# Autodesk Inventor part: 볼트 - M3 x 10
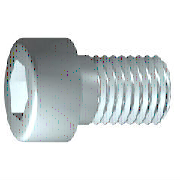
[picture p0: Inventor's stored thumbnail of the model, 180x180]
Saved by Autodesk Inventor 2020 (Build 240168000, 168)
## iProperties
Created: 2012-02
Part Number: 볼트 - M3 x 10
Material: 스테인리스강
Description: 6각 소켓 머리 캡 나사
Document SubType Name: Modeling
Standard: ISO 4762
Designer: mduedu
Standard Revision: Fourth edition 2004-03-01
Standards Organization: ISO
Language: ko-KR
Size Designation: M3 x 10
Categories: <MemberInstance><Categories><Category DisplayName="조임쇠" InternalName="e4da775c-781d-43d5-af7c-5136215cf5a6" Mnemonic="FSTN"><Category DisplayName="볼트" InternalN
Density: 8.08 g/cm^3
Mass: 1.0701 g
Surface Area: 2.01851 cm^2
Volume: 0.132438 cm^3
Appearance: 반광택
IsCustomPart: 0
Author: mduedu
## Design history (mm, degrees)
sketch "스케치1"
  geometry: L1 (-0.867, 0)-(10, 0); L2 (10, 0)-(10, 1.5); L3 (10, 1.5)-(1.25, 1.5); L4 (1.25, 1.5)-(0.943, 1.5); L5 (0.943, 1.5)-(0, 1.5); L6 (0, 1.5)-(0, 2.75); L7 (0, 2.75)-(-3, 2.75); L8 (-3, 2.75)-(-3, 1.443); L9 (-3, 1.443)-(-1.7, 1.443); L10 (-1.7, 1.443)-(-0.867, 0); L11 (-5.6, 0)-(12.6, 0) reference; L12 (0, -0.55)-(0, 3.3) reference; L13 (1.25, 1.5)-(0, 1.5)
  constraints: 22 end point, 6 parallel, 2 collinear, 2 perpendicular, 1 horizontal, 1 point on line
  dimensions: "d1" = 8.75 distance from line of L3.end L2 (= GEL); "d2" = 0.30683 distance of L4.end L3.end (computed from GAL); "d3" = 3 distance between parallel lines of L8 L6 (= KOH); "d4" = 1.3 distance of L8.end L9.end (= INTI); "d5" = 60 deg angle of L10 L1; "d6" = 3 diameter of L3 L1 (= GD); "d7" = 3 diameter of L5 L1 (= BDM); "d8" = 2.88675 diameter of L9 L1 (= 1.1547 x SW); "d9" = 5.5 diameter of L7 L1 (= KOD); "d26" = 10 distance between parallel lines of L12 L2 (= NLG)
revolve "본체" sketch "스케치1" stored, may be unused: angle "d10" = 90 deg
sketch "스케치2"
  geometry: L1 (0, -3.85)-(0, 3.85) reference; L2 (-3.85, 0)-(3.85, 0) reference; L3 (1.443, 0)-(0.722, -1.25); L4 (0.722, -1.25)-(-0.722, -1.25); L5 (-0.722, -1.25)-(-1.443, 0); L6 (-1.443, 0)-(-0.722, 1.25); L7 (-0.722, 1.25)-(0.722, 1.25); L8 (0.722, 1.25)-(1.443, 0); 2 further points
  constraints: 12 end point, 1 coincident, 1 horizontal alignment, 1 point on line, 12 other
extrude "슬롯" join sketch "스케치2" stored distance "d11" = 10; taper "d12" = 0 deg
workplane "Work Plane1"
fillet "Fillet2" dims "d30" = 0.1 (= R)
body "Solid1"
fillet "모깎기1" dims "d17" = 0.3 (= RR)
feature "스레드" dims "d13" = 8.75 (= GEL), "d14" = 0
chamfer "모따기1" distance "d15" = 0.30673 (= -0.5 x SPD + 0.5 x GD); stored, may be unused: second distance "d16" = 0.30673 (= GUL), angle "d27" = 45 deg
other parameters: "GD" = 3 [user parameter; used in 2 equation terms], "NLG" = 10 [user parameter; used in 1 equation term], "GEL" = 8.75 [user parameter; used in 2 equation terms], "KOD" = 5.5 [user parameter; used in 1 equation term], "KOH" = 3 [user parameter; used in 1 equation term], "INTI" = 1.3 [user parameter; used in 1 equation term], "GAL" = 0.30673 (= 0.61345 x PTC) [user parameter; used in 1 equation term], "GUL" = 0.30673 (= 0.61345 x PTC) [user parameter; used in 1 equation term], "BDM" = 3 (= NND) [user parameter; used in 1 equation term], "SW" = 2.5 [user parameter; used in 2 equation terms], "RR" = 0.3 [user parameter; used in 1 equation term], "SPD" = 2.38655 (= NND - 1.2269 x PTC) [user parameter; used in 1 equation term], "d19" = 0, "d28" = 0, "d29" = 0, "R" = 0.1 [user parameter; used in 1 equation term], "TOA" = 30 deg [user parameter], "GD1" = 2.38655 (= THREADDIA - 1.2269 x PTC) [user parameter], "THREADDIA" = 3 [user parameter; used in 1 equation term], "FAWI" = 45 deg [user parameter], "PTC" = 0.5 [user parameter; used in 5 equation terms], "NND" = 3 [user parameter; used in 2 equation terms], "E0" = 2.8875 (= 1.155 x SW) [user parameter]
